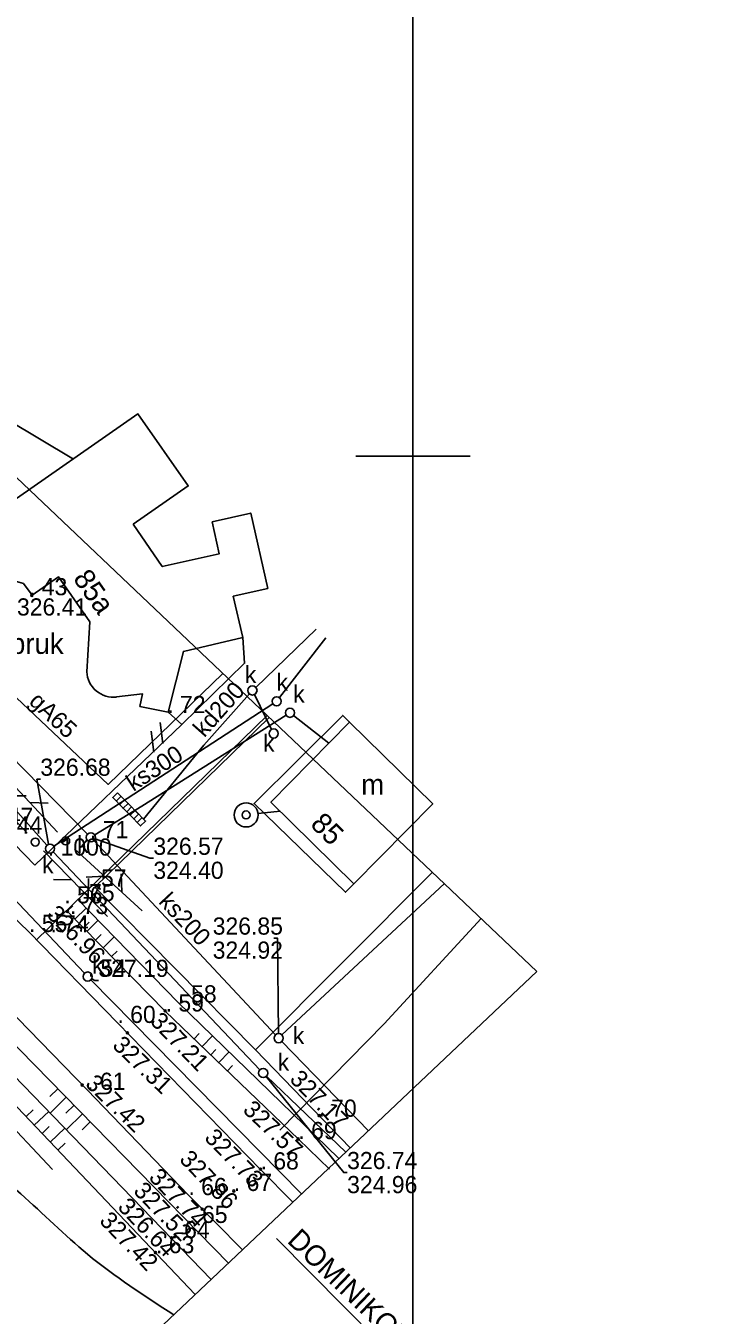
# Model space of a CAD drawing. Extents: x 4632591 to 4653165, y 5351032 to 5369868.
# Drawn here: x 4644766.2 to 4644826.8, y 5358525 to 5358637.6 of the extents above; entities that cross this region are included whole.
import ezdxf

# ---------------------------------------------------------------- set-up
doc = ezdxf.new("R2010")
doc.units = 0
for name, color, linetype in [('EADPD_238', 7, 'Continuous'), ('EBUPP_312', 7, 'Continuous'), ('EDZPX_299', 7, 'Continuous'), ('SDRPK_420', 7, 'Continuous'), ('SDRPK_423', 7, 'Continuous'), ('SDRPK_432', 7, 'Continuous'), ('SZOPO_902', 7, 'Continuous'), ('SZOPO_903', 7, 'Continuous'), ('UEEPA_510', 7, 'Continuous'), ('UEETA_515', 7, 'Continuous'), ('UEETA_516', 7, 'Continuous'), ('UGGPO_553', 7, 'Continuous'), ('UKKPA_506', 7, 'Continuous'), ('UKKPA_509', 7, 'Continuous'), ('UKKPB_562', 7, 'Continuous'), ('UTTTA_521', 7, 'Continuous'), ('UWWPA_907', 7, 'Continuous'), ('UWWPO_581', 7, 'Continuous'), ('Warstwa 40', 7, 'Continuous'), ('Warstwa 60', 7, 'Continuous'), ('Warstwa 62', 7, 'Continuous'), ('WUKPS_403', 7, 'Continuous'), ('WUKPS_820', 7, 'Continuous'), ('WUKPS_823', 7, 'Continuous'), ('WUKPS_824', 7, 'Continuous'), ('WWRPH_811', 7, 'Continuous')]:
    doc.layers.add(name, color=color, linetype=linetype)

msp = doc.modelspace()

# ---------------------------------------------------------------- linework, layer by layer
at = {"layer": 'EBUPP_312'}
for points in [[(4644760.47, 5358595.72), (4644760.54, 5358596.09), (4644764.13, 5358595.43), (4644775.98, 5358603.7), (4644780.37, 5358597.41), (4644775.58, 5358594.07)], [(4644775.58, 5358594.07), (4644778.1, 5358590.37), (4644783.09, 5358591.5), (4644782.47, 5358594.27), (4644785.83, 5358595.04), (4644787.32, 5358588.46), (4644784.31, 5358587.78), (4644785.13, 5358584.19), (4644779.96, 5358582.97), (4644778.61, 5358577.67), (4644776.16, 5358578.16), (4644776.38, 5358579.27), (4644774.11, 5358578.99)], [(4644771.51, 5358581.18), (4644771.79, 5358585.56), (4644769.05, 5358589.47), (4644766.74, 5358587.89), (4644765.98, 5358588.9), (4644760.46, 5358590.46)]]:
    msp.add_lwpolyline(points, dxfattribs=at)
msp.add_lwpolyline([(4644794.85, 5358562.68), (4644787.6, 5358569.8), (4644794.46, 5358576.8), (4644801.72, 5358569.67)], close=True, dxfattribs=at)
msp.add_arc((4644773.84, 5358581.3), 2.33, 182.8118, 276.8732, dxfattribs=at)
at = {"layer": 'EDZPX_299'}
for p, q in [((4644777.37, 5358574.17), (4644777.13, 5358576.01)), ((4644778.17, 5358574.93), (4644777.92, 5358576.77))]:
    msp.add_line(p, q, dxfattribs=at)
at = {"layer": 'SDRPK_420'}
msp.add_line((4644787.26, 5358577.38), (4644767.13, 5358557.79), dxfattribs=at)
for points in [[(4644716.77, 5358607.78), (4644736.68, 5358588.98), (4644743.87, 5358581.58), (4644750.16, 5358575.12), (4644760.49, 5358564.21), (4644766.47, 5358558.47), (4644774.19, 5358550.53), (4644786.69, 5358537.74), (4644789.51, 5358534.89)], [(4644712.76, 5358603.26), (4644713.95, 5358602.19), (4644735.11, 5358581.89), (4644746.11, 5358570.7), (4644757.33, 5358559.27), (4644771.55, 5358544.69), (4644780.39, 5358535.5), (4644785.1, 5358530.72)]]:
    msp.add_lwpolyline(points, dxfattribs=at)
at = {"layer": 'SDRPK_423'}
msp.add_line((4644766.97, 5358564.32), (4644764.29, 5358567.07), dxfattribs=at)
for points in [[(4644770.35, 5358599.76), (4644761.7, 5358604.91), (4644748.36, 5358589.39), (4644741.21, 5358589.24)], [(4644778.61, 5358577.67), (4644779.81, 5358576.59), (4644766.97, 5358564.32)], [(4644794.85, 5358562.68), (4644794.12, 5358561.94), (4644786.12, 5358569.68), (4644793.87, 5358577.38), (4644794.46, 5358576.8)]]:
    msp.add_lwpolyline(points, dxfattribs=at)
at = {"layer": 'SDRPK_432'}
msp.add_lwpolyline([(4644799.86, 5358519.82), (4644788.08, 5358531.71)], dxfattribs=at)
at = {"layer": 'SZOPO_902'}
msp.add_line((4644786.25, 5358548.18), (4644794.52, 5358539.62), dxfattribs=at)
for points in [[(4644778.61, 5358577.67), (4644779.81, 5358576.59), (4644785.3, 5358581.94), (4644785.13, 5358584.19)], [(4644787.44, 5358577.21), (4644772.23, 5358562.39), (4644786.25, 5358548.18), (4644801.7, 5358563.69)]]:
    msp.add_lwpolyline(points, dxfattribs=at)
at = {"layer": 'SZOPO_903'}
msp.add_line((4644772.23, 5358562.39), (4644786.25, 5358548.18), dxfattribs=at)
at = {"layer": 'UEEPA_510'}
for centre in [(4644767.02, 5358566.32), (4644769.67, 5358566.43)]:
    msp.add_circle(centre, 0.35, dxfattribs=at)
at = {"layer": 'UEETA_515'}
msp.add_line((4644765.42, 5358570.37), (4644766.22, 5358570.37), dxfattribs=at)
at = {"layer": 'UEETA_516'}
msp.add_line((4644763.04, 5358543.56), (4644768.52, 5358537.73), dxfattribs=at)
at = {"layer": 'UGGPO_553'}
msp.add_lwpolyline([(4644783.41, 5358581.03), (4644773.38, 5358571.35), (4644744.52, 5358598.63), (4644727.75, 5358614.29), (4644724.77, 5358616.81)], dxfattribs=at)
at = {"layer": 'UKKPA_506'}
for points in [[(4644767.46, 5358571.81), (4644767.16, 5358571.81), (4644768.17, 5358566.13)], [(4644777.33, 5358564.91), (4644777.03, 5358564.91), (4644772.25, 5358566.6)], [(4644787.86, 5358557.94), (4644788.16, 5358557.94), (4644788.27, 5358549.6)], [(4644772.53, 5358554.25), (4644772.23, 5358554.25), (4644771.95, 5358554.39)], [(4644794.25, 5358537.47), (4644793.95, 5358537.47), (4644787.17, 5358545.85)]]:
    msp.add_lwpolyline(points, dxfattribs=at)
for centre in [(4644785.98, 5358579.56), (4644788.09, 5358578.61), (4644789.26, 5358577.61), (4644787.84, 5358575.8), (4644771.87, 5358566.73), (4644768.3, 5358565.75), (4644771.6, 5358554.58), (4644788.27, 5358549.2), (4644786.92, 5358546.16)]:
    msp.add_circle(centre, 0.4, dxfattribs=at)
at = {"layer": 'UKKPA_509'}
for p, q in [((4644774.52, 5358570.32), (4644774.08, 5358569.9)), ((4644774.39, 5358569.59), (4644774.82, 5358570.01)), ((4644775.43, 5358569.39), (4644775, 5358568.97)), ((4644775.3, 5358568.66), (4644775.74, 5358569.08)), ((4644776.04, 5358568.77), (4644775.61, 5358568.35)), ((4644775.91, 5358568.04), (4644776.35, 5358568.46))]:
    msp.add_line(p, q, dxfattribs=at)
for points in [[(4644774.21, 5358570.63), (4644775.13, 5358569.7), (4644774.69, 5358569.28), (4644773.78, 5358570.21)], [(4644775.13, 5358569.7), (4644776.04, 5358568.77), (4644775.61, 5358568.35), (4644774.69, 5358569.28)], [(4644775.74, 5358569.08), (4644776.65, 5358568.15), (4644776.22, 5358567.73), (4644775.3, 5358568.66)]]:
    msp.add_lwpolyline(points, close=True, dxfattribs=at)
at = {"layer": 'UKKPB_562'}
for p, q in [((4644768.03, 5358566.05), (4644749.14, 5358587.24)), ((4644786.27, 5358579.83), (4644791.56, 5358584.92)), ((4644788.33, 5358578.93), (4644792.39, 5358584.16)), ((4644787.75, 5358578.4), (4644768.63, 5358565.97)), ((4644786.16, 5358579.2), (4644787.66, 5358576.16)), ((4644789.58, 5358577.36), (4644792.65, 5358574.95)), ((4644786.64, 5358546.45), (4644768.57, 5358565.46)), ((4644788.56, 5358549.48), (4644802.74, 5358562.7)), ((4644787.21, 5358545.89), (4644794.14, 5358539.26))]:
    msp.add_line(p, q, dxfattribs=at)
for points in [[(4644749.74, 5358589.28), (4644771.59, 5358567.02)], [(4644776.48, 5358568.33), (4644781.74, 5358574.78), (4644785.72, 5358579.26)], [(4644749.94, 5358577.39), (4644771.32, 5358554.87)], [(4644772.22, 5358566.94), (4644776.33, 5358569.46), (4644788.92, 5358577.39)], [(4644772.15, 5358566.44), (4644788, 5358549.5)], [(4644805.96, 5358559.65), (4644797.47, 5358550.45), (4644788.38, 5358541.18)], [(4644771.88, 5358554.29), (4644790.27, 5358535.6)], [(4644788.55, 5358548.92), (4644796.11, 5358541.12)]]:
    msp.add_lwpolyline(points, dxfattribs=at)
at = {"layer": 'UTTTA_521'}
for p, q in [((4644766.31, 5358567.09), (4644760.85, 5358572.93)), ((4644768.95, 5358567.2), (4644763.49, 5358573.04)), ((4644766.54, 5358569.78), (4644768.14, 5358569.72)), ((4644767.75, 5358565.57), (4644773.32, 5358559.82)), ((4644770.44, 5358565.72), (4644776.35, 5358560.33)), ((4644774.58, 5358561.95), (4644774.51, 5358563.55)), ((4644770.21, 5358563.03), (4644768.61, 5358563.06)), ((4644773.05, 5358563.34), (4644771.45, 5358563.27)), ((4644771.65, 5358561.55), (4644771.68, 5358563.14))]:
    msp.add_line(p, q, dxfattribs=at)
at = {"layer": 'UWWPA_907'}
for radius in [1.05, 0.35]:
    msp.add_circle((4644785.43, 5358568.69), radius, dxfattribs=at)
at = {"layer": 'UWWPO_581'}
msp.add_line((4644786.47, 5358568.81), (4644788.4, 5358569.02), dxfattribs=at)
at = {"layer": 'Warstwa 40'}
msp.add_lwpolyline([(4644810.83, 5358555.03), (4644734.32, 5358627.59), (4644688.9, 5358576.34), (4644696.21, 5358541.05), (4644665.65, 5358513.08), (4644675.21, 5358482.87), (4644634.26, 5358446.15), (4644624.66, 5358448.08), (4644610.34, 5358444.41), (4644593.08, 5358445.77), (4644584.82, 5358446.42), (4644558.95, 5358331.35), (4644690.29, 5358293.2), (4644705.73, 5358386.52), (4644692.29, 5358404.57), (4644776.59, 5358522.67)], close=True, dxfattribs=at)
at = {"layer": 'Warstwa 60'}
for p, q in [((4644795, 5358600), (4644800, 5358600)), ((4644800, 5358600), (4644805, 5358600))]:
    msp.add_line(p, q, dxfattribs=at)
for points in [[(4644000, 5358500), (4644000, 5359000), (4644800, 5359000), (4644800, 5358500)], [(4644800, 5358500), (4644800, 5359000), (4645600, 5359000), (4645600, 5358500)]]:
    msp.add_lwpolyline(points, close=True, dxfattribs=at)
at = {"layer": 'WUKPS_403'}
for centre in [(4644766.72, 5358587.86), (4644769.82, 5358560.27), (4644778.36, 5358551.59), (4644775.06, 5358549.66), (4644771.12, 5358545.11), (4644791.8, 5358542.44), (4644789.98, 5358540.4), (4644786.68, 5358537.76), (4644784.35, 5358535.86), (4644781.6, 5358534.28), (4644780.44, 5358533.11), (4644778.91, 5358531.77), (4644777.52, 5358530.48)]:
    msp.add_circle(centre, 0.09, dxfattribs=at)
at = {"layer": 'WUKPS_820'}
for p, q in [((4644769.8, 5358560.28), (4644770.29, 5358560.77)), ((4644769.8, 5358560.28), (4644770.29, 5358560.77)), ((4644769.8, 5358560.28), (4644770.29, 5358560.77)), ((4644770.48, 5358559.59), (4644771.47, 5358560.56)), ((4644770.48, 5358559.59), (4644771.47, 5358560.56)), ((4644770.48, 5358559.59), (4644771.47, 5358560.56)), ((4644770.85, 5358559.22), (4644771.34, 5358559.7)), ((4644771.22, 5358558.84), (4644771.71, 5358559.33)), ((4644771.22, 5358558.84), (4644771.71, 5358559.33)), ((4644771.22, 5358558.84), (4644771.71, 5358559.33)), ((4644771.53, 5358558.52), (4644772.51, 5358559.49)), ((4644772.27, 5358557.77), (4644772.76, 5358558.26)), ((4644772.95, 5358557.08), (4644773.92, 5358558.04)), ((4644773.68, 5358556.33), (4644774.17, 5358556.81)), ((4644780.88, 5358549.15), (4644781.34, 5358549.62)), ((4644781.58, 5358548.47), (4644782.49, 5358549.42)), ((4644782.34, 5358547.75), (4644782.79, 5358548.22)), ((4644783.04, 5358547.07), (4644783.94, 5358548.02)), ((4644783.79, 5358546.35), (4644784.24, 5358546.82)), ((4644768.99, 5358544.79), (4644768.29, 5358544.1)), ((4644769.72, 5358544.04), (4644768.32, 5358542.66)), ((4644770.41, 5358543.34), (4644769.7, 5358542.65)), ((4644766.21, 5358542.36), (4644766.83, 5358542.95)), ((4644766.93, 5358541.6), (4644768.19, 5358542.79)), ((4644771.14, 5358542.59), (4644769.72, 5358541.21)), ((4644767.61, 5358540.89), (4644768.24, 5358541.49)), ((4644768.33, 5358540.13), (4644769.6, 5358541.34)), ((4644771.82, 5358541.9), (4644771.11, 5358541.2)), ((4644769, 5358539.42), (4644769.64, 5358540.03))]:
    msp.add_line(p, q, dxfattribs=at)
at = {"layer": 'WUKPS_823'}
for points in [[(4644783.89, 5358529.57), (4644744.81, 5358569.5), (4644739.48, 5358575.37)], [(4644780.99, 5358526.83), (4644742.7, 5358567.06), (4644738.78, 5358571.28)], [(4644769.75, 5358560.34), (4644778.4, 5358551.53), (4644789.99, 5358540.39), (4644792.7, 5358537.78)]]:
    msp.add_lwpolyline(points, dxfattribs=at)
at = {"layer": 'WUKPS_824'}
for points in [[(4644782.38, 5358528.14), (4644743.56, 5358568.22), (4644738.44, 5358574.02)], [(4644770.74, 5358561.3), (4644779.51, 5358552.32), (4644793.5, 5358538.74)]]:
    msp.add_lwpolyline(points, dxfattribs=at)
at = {"layer": 'WWRPH_811'}
msp.add_spline([(4644779.11, 5358525.05), (4644771.58, 5358530.34), (4644759.35, 5358539.86), (4644757.99, 5358540.39), (4644757.32, 5358540.65), (4644756.64, 5358540.89), (4644755.5, 5358541.29), (4644754.37, 5358541.71)], degree=3, dxfattribs=at)

# ---------------------------------------------------------------- texts
at = {"layer": 'EADPD_238'}
for s, rotation, p in [('85a', 305.0966, (4644770.26, 5358589.32)), ('85', 315.5312, (4644790.95, 5358567.78))]:
    msp.add_text(s, height=1.8, rotation=rotation, dxfattribs=at).set_placement(p)
at = {"layer": 'EBUPP_312'}
msp.add_text('m', height=1.8, dxfattribs=at).set_placement((4644795.48, 5358570.45))
at = {"layer": 'SDRPK_423'}
msp.add_text('k.bruk', height=1.8, dxfattribs=at).set_placement((4644762.94, 5358582.75))
at = {"layer": 'SDRPK_432'}
msp.add_text('DOMINIKOWICE', height=1.8, rotation=316.1883, dxfattribs=at).set_placement((4644788.93, 5358531.43))
at = {"layer": 'UGGPO_553'}
msp.add_text('gA65', height=1.5, rotation=316.6234, dxfattribs=at).set_placement((4644766.38, 5358578.48))
at = {"layer": 'UKKPA_506'}
for s, p in [('k', (4644785.32, 5358580.2)), ('k', (4644788.09, 5358579.53)), ('k', (4644789.54, 5358578.5)), ('k', (4644786.91, 5358574.21)), ('326.68', (4644767.46, 5358572.11)), ('k', (4644770.67, 5358565.37)), ('326.57', (4644777.33, 5358565.21)), ('k', (4644767.61, 5358563.6)), ('324.40', (4644777.33, 5358563.11)), ('326.85', (4644782.51, 5358558.24)), ('324.92', (4644782.51, 5358556.14)), ('k', (4644771.98, 5358554.84)), ('327.19', (4644772.53, 5358554.55)), ('k', (4644789.51, 5358548.68)), ('k', (4644788.19, 5358546.36)), ('326.74', (4644794.25, 5358537.77)), ('324.96', (4644794.25, 5358535.67))]:
    msp.add_text(s, height=1.5, dxfattribs=at).set_placement(p)
at = {"layer": 'UKKPB_562'}
for s, rotation, p in [('kd200', 48.3856, (4644781.78, 5358575.39)), ('ks300', 33.0213, (4644775.58, 5358570.69)), ('ks200', 313.086, (4644777.71, 5358561.05))]:
    msp.add_text(s, height=1.5, rotation=rotation, dxfattribs=at).set_placement(p)
at = {"layer": 'Warstwa 62'}
for s, p in [('. 43', (4644766.47, 5358587.87)), ('. 72', (4644778.54, 5358577.58)), ('. 47', (4644763.5, 5358567.82)), ('. 44', (4644764.29, 5358567.07)), ('. 71', (4644771.8, 5358566.66)), ('. 1000', (4644768.11, 5358565.14)), ('. 1000', (4644768.11, 5358565.14)), ('. 57', (4644771.64, 5358562.44)), ('. 56', (4644769.55, 5358560.97)), ('. 75', (4644770.6, 5358561.16)), ('. 73', (4644770.04, 5358560.04)), ('. 55', (4644766.47, 5358558.47)), ('. 74', (4644768.34, 5358558.44)), ('. 54', (4644771.6, 5358554.58)), ('. 58', (4644779.51, 5358552.32)), ('. 59', (4644778.4, 5358551.53)), ('. 60', (4644774.19, 5358550.53)), ('. 61', (4644771.55, 5358544.69)), ('. 70', (4644791.74, 5358542.34)), ('. 69', (4644789.99, 5358540.39)), ('. 68', (4644786.69, 5358537.74)), ('. 66', (4644780.39, 5358535.5)), ('. 67', (4644784.35, 5358535.86)), ('. 65', (4644780.46, 5358533.07)), ('. 64', (4644778.9, 5358531.73)), ('. 63', (4644777.56, 5358530.43))]:
    msp.add_text(s, height=1.5, dxfattribs=at).set_placement(p)
at = {"layer": 'WUKPS_403'}
msp.add_text('326.41', height=1.5, dxfattribs=at).set_placement((4644765.42, 5358586.1))
for s, rotation, p in [('326.96', 314.1754, (4644767.93, 5358559.92)), ('327.21', 314.1754, (4644776.97, 5358550.59)), ('327.31', 316.1883, (4644773.67, 5358548.47)), ('327.42', 316.1883, (4644771.3, 5358545.11)), ('327.17', 314.0422, (4644789.15, 5358545.54)), ('327.57', 316.1342, (4644785.06, 5358542.84)), ('327.73', 314.343, (4644781.71, 5358540.42)), ('327.86', 313.8829, (4644779.52, 5358538.55)), ('327.74', 313.8829, (4644776.85, 5358536.97)), ('327.52', 313.8829, (4644775.51, 5358535.78)), ('326.64', 313.8829, (4644774.13, 5358534.39)), ('327.42', 313.8829, (4644772.54, 5358533.18))]:
    msp.add_text(s, height=1.5, rotation=rotation, dxfattribs=at).set_placement(p)

doc.saveas('drawing.dxf')
